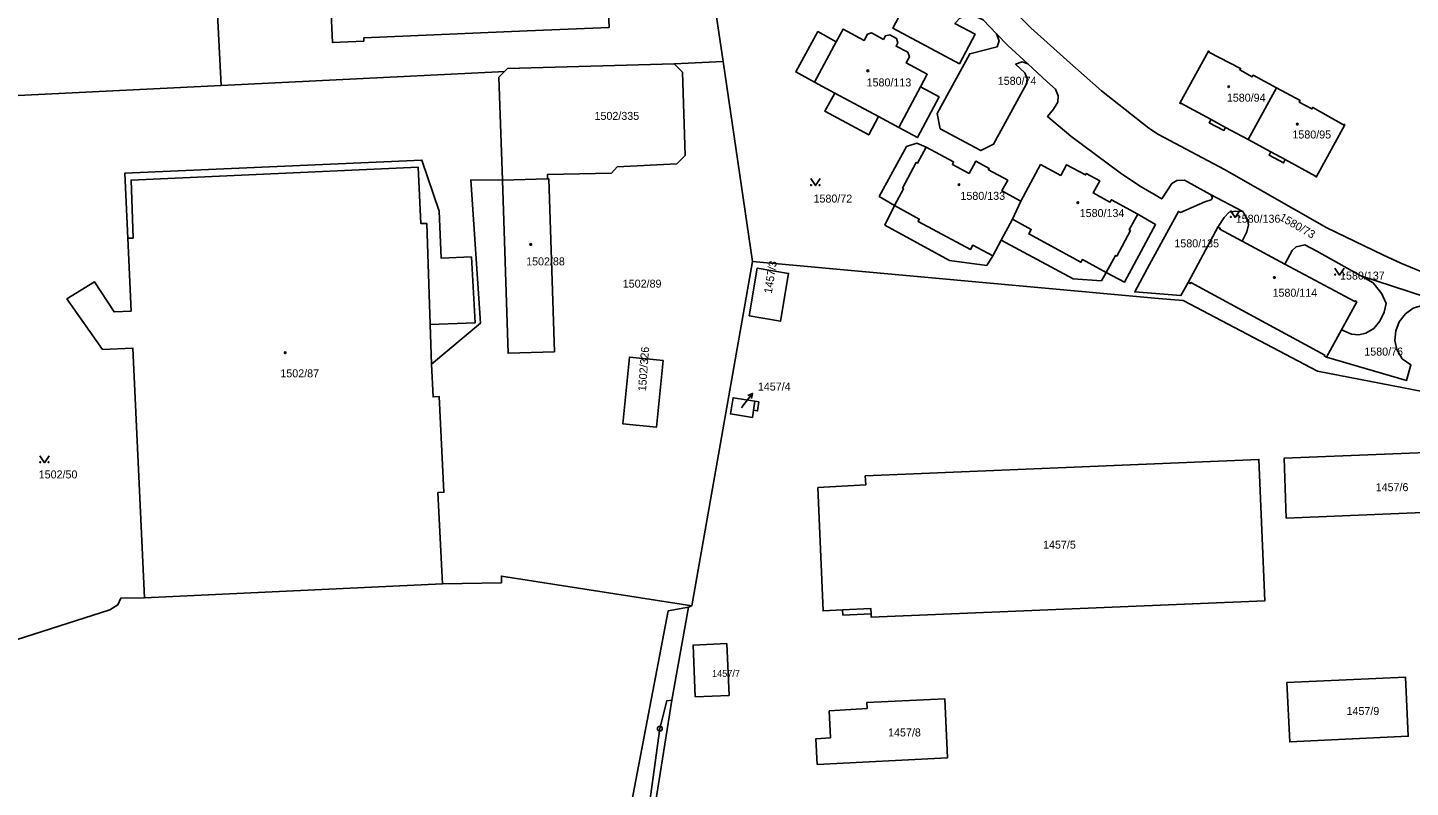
# Model space of a CAD drawing. Extents: x -737240 to -735272, y -1119606 to -1117878.
# Drawn here: x -736364.4 to -736070.6, y -1118481.5 to -1118320.2 of the extents above; entities that cross this region are included whole.
import ezdxf

# ---------------------------------------------------------------- set-up
doc = ezdxf.new("R2010")
doc.units = 0
for name, color, linetype in [('Level 1', 7, 'Continuous'), ('Level 16', 7, 'Continuous'), ('Level 18', 7, 'Continuous'), ('Level 19', 7, 'Continuous'), ('Level 25', 7, 'Continuous'), ('Level 4', 7, 'Continuous')]:
    doc.layers.add(name, color=color, linetype=linetype)

msp = doc.modelspace()

# ---------------------------------------------------------------- linework, layer by layer
at = {"layer": 'Level 1'}
for p, q in [((-736221.31, -1118295.84), (-736216.6, -1118327.37)), ((-736161.4, -1118318.52), (-736158.52, -1118321.48)), ((-736216.6, -1118327.37), (-736227.02, -1118327.84)), ((-736216.6, -1118327.37), (-736210.35, -1118369.86)), ((-736197.2, -1118331.72), (-736192.89, -1118334.04)), ((-736099.05, -1118332.96), (-736105.07, -1118343.93)), ((-736183.59, -1118339.04), (-736179.32, -1118341.34)), ((-736109.85, -1118341.34), (-736105.07, -1118343.93)), ((-736105.07, -1118343.93), (-736100.26, -1118346.53)), ((-736263.51, -1118352.52), (-736253.92, -1118352.29)), ((-736155.13, -1118360.86), (-736153.37, -1118357.01)), ((-736106.2, -1118359.23), (-736113.2, -1118355.5)), ((-736157.52, -1118365.27), (-736155.13, -1118360.86)), ((-736117.84, -1118374.26), (-736111.5, -1118362.52)), ((-736159.33, -1118368.64), (-736157.52, -1118365.27)), ((-736097.3, -1118370.36), (-736106.34, -1118365.52)), ((-736223.29, -1118442.99), (-736210.35, -1118369.86)), ((-736059.31, -1118379.99), (-736081.16, -1118372.84)), ((-736278.61, -1118391.65), (-736278.89, -1118383.2)), ((-736088.43, -1118390.14), (-736085.25, -1118384.34)), ((-736339.59, -1118441.28), (-736276.27, -1118438.27)), ((-736227.49, -1118462.99), (-736223.96, -1118443.23)), ((-736223.96, -1118443.23), (-736223.29, -1118442.99))]:
    msp.add_line(p, q, dxfattribs=at)
for points in [[(-736068.55, -1118371.85), (-736072.64, -1118370.2), (-736076.44, -1118368.41), (-736088.36, -1118362.67), (-736110.12, -1118350.32), (-736124.12, -1118342.88), (-736126.16, -1118341.48), (-736136.25, -1118333.56), (-736143.63, -1118327.06), (-736151.23, -1118320.2), (-736160.8, -1118310.46), (-736177.91, -1118292.84), (-736196.9, -1118273.97)], [(-736294.67, -1118283.81), (-736294.71, -1118283.08), (-736301.44, -1118283.43), (-736299.65, -1118323.31), (-736292.98, -1118323.01), (-736293, -1118322.34), (-736258.25, -1118320.8), (-736240.85, -1118320.09), (-736242.53, -1118281.51), (-736259.92, -1118282.25), (-736294.67, -1118283.81)], [(-736323.26, -1118332.43), (-736325.03, -1118297.95), (-736380.42, -1118300.27), (-736381.78, -1118300.94), (-736382.38, -1118302.33), (-736380.97, -1118335.25)], [(-736172.1, -1118307.65), (-736171, -1118309.11), (-736170.78, -1118310.09), (-736170.84, -1118311.64), (-736171.13, -1118312.71), (-736171.64, -1118313.71), (-736175.96, -1118311.46), (-736180.58, -1118320.28), (-736166.41, -1118327.84), (-736163.09, -1118321.53), (-736167.36, -1118319.29), (-736166.33, -1118318.15), (-736164.95, -1118317.56), (-736163.41, -1118317.56), (-736161.4, -1118318.52)], [(-736192.59, -1118323.14), (-736196.5, -1118320.98), (-736201.21, -1118329.56), (-736197.2, -1118331.72)], [(-736174.71, -1118332.75), (-736173.26, -1118330.06), (-736177.73, -1118327.66), (-736177.03, -1118326.38), (-736177.35, -1118325.39), (-736179.87, -1118324.1), (-736179.48, -1118323.4), (-736179.78, -1118322.45), (-736181.19, -1118321.68), (-736182.13, -1118321.87), (-736182.56, -1118322.65), (-736185.07, -1118321.29), (-736185.98, -1118321.55), (-736186.68, -1118322.85), (-736191.14, -1118320.45), (-736192.59, -1118323.14)], [(-736158.52, -1118321.48), (-736157.94, -1118322.93), (-736158.41, -1118324.22), (-736164.24, -1118325.69), (-736171.13, -1118338.38), (-736170.54, -1118341.64), (-736161.89, -1118346.28), (-736159.17, -1118344.92), (-736152.17, -1118332.06), (-736151.99, -1118330.98), (-736152.51, -1118329.78), (-736154.47, -1118327.94), (-736153.08, -1118327.41), (-736151.91, -1118327.84)], [(-736151.91, -1118327.84), (-736156.1, -1118323.97), (-736158.52, -1118321.48)], [(-736227.02, -1118327.84), (-736262.47, -1118328.86), (-736263.09, -1118329.48)], [(-736253.92, -1118352.29), (-736253.91, -1118351.34), (-736240.31, -1118351.05), (-736239.12, -1118349.69), (-736226.46, -1118349.08), (-736224.71, -1118347.31), (-736225.29, -1118329.61), (-736227.02, -1118327.84)], [(-736151.91, -1118327.84), (-736147.88, -1118331.57), (-736145.97, -1118333.22), (-736145.45, -1118334.65), (-736145.53, -1118336), (-736146.42, -1118337.49), (-736147.72, -1118339), (-736142.73, -1118343.24), (-736132.28, -1118350.99), (-736128.12, -1118353.73), (-736123.41, -1118356.52), (-736121.25, -1118353.28), (-736120.22, -1118352.62), (-736118.6, -1118352.53), (-736113.2, -1118355.5)], [(-736099.05, -1118332.96), (-736104.03, -1118330.26), (-736104.2, -1118330.57), (-736106.83, -1118329.14), (-736106.67, -1118328.83), (-736113.41, -1118325.36), (-736113.34, -1118325.22), (-736113.5, -1118325.14), (-736119.62, -1118336.2), (-736119.44, -1118336.3), (-736119.39, -1118336.19), (-736112.94, -1118339.68)], [(-736263.09, -1118329.48), (-736264.33, -1118329.54), (-736323.26, -1118332.43)], [(-736263.09, -1118329.48), (-736264.29, -1118330.68), (-736263.51, -1118352.52)], [(-736380.97, -1118335.25), (-736379.45, -1118335.18), (-736323.26, -1118332.43)], [(-736179.32, -1118341.34), (-736175.34, -1118343.49), (-736170.74, -1118334.88), (-736174.71, -1118332.75)], [(-736097.18, -1118348.19), (-736090.73, -1118351.68), (-736090.79, -1118351.78), (-736090.61, -1118351.88), (-736084.55, -1118340.79), (-736084.72, -1118340.69), (-736084.8, -1118340.83), (-736091.36, -1118337.1), (-736091.53, -1118337.41), (-736094.21, -1118335.96), (-736094.05, -1118335.66), (-736099.05, -1118332.96)], [(-736192.89, -1118334.04), (-736195.02, -1118337.92), (-736185.69, -1118342.95), (-736183.59, -1118339.04)], [(-736112.94, -1118339.68), (-736113.38, -1118340.34), (-736110.21, -1118342), (-736109.85, -1118341.34)], [(-736173.49, -1118345.53), (-736175.48, -1118344.7), (-736177.69, -1118345.4), (-736183.44, -1118355.99), (-736180.2, -1118357.95)], [(-736153.37, -1118357.01), (-736157.39, -1118354.84), (-736156.15, -1118352.56), (-736160.24, -1118350.34), (-736160.12, -1118350.05), (-736162.96, -1118348.52), (-736164.35, -1118351.11), (-736167.9, -1118349.19), (-736167.65, -1118348.66), (-736173.49, -1118345.53)], [(-736278.89, -1118383.2), (-736269.34, -1118382.88), (-736270.12, -1118368.85), (-736276.55, -1118369.1), (-736276.94, -1118359.16), (-736280.62, -1118348.27), (-736343.76, -1118351.09), (-736343.12, -1118364.89)], [(-736100.26, -1118346.53), (-736100.63, -1118347.21), (-736097.55, -1118348.88), (-736097.18, -1118348.19)], [(-736128.51, -1118359.75), (-736134.13, -1118356.71), (-736134.43, -1118357.19), (-736137.97, -1118355.27), (-736136.61, -1118352.7), (-736139.47, -1118351.16), (-736139.62, -1118351.44), (-736143.64, -1118349.26), (-736144.88, -1118351.55), (-736149.18, -1118349.24), (-736153.37, -1118357.01)], [(-736263.51, -1118352.52), (-736270.26, -1118352.5), (-736268.18, -1118382.94), (-736278.61, -1118391.65)], [(-736253.92, -1118352.29), (-736253.63, -1118352.28), (-736252.49, -1118389.01), (-736262.31, -1118389.33), (-736263.51, -1118352.52)], [(-736113.2, -1118355.5), (-736112.91, -1118355.84), (-736112.66, -1118356.27), (-736112.96, -1118356.7), (-736114.3, -1118357.13), (-736119.42, -1118359.4), (-736119.87, -1118359.2), (-736126.02, -1118370.43), (-736129.18, -1118376.27), (-736119.36, -1118377.08), (-736117.84, -1118374.26)], [(-736180.2, -1118357.95), (-736182.26, -1118362.08), (-736168.54, -1118369.59), (-736160.62, -1118370.71), (-736159.33, -1118368.64)], [(-736135.22, -1118372.18), (-736131.36, -1118374.21), (-736124.74, -1118361.99), (-736128.51, -1118359.75)], [(-736111.5, -1118362.52), (-736110.16, -1118360.45), (-736109.08, -1118359.37), (-736107.74, -1118359.11), (-736106.2, -1118359.23)], [(-736106.34, -1118365.52), (-736105.32, -1118363.55), (-736105.02, -1118362.06), (-736105.2, -1118360.89), (-736106.2, -1118359.23)], [(-736111.5, -1118362.52), (-736110.97, -1118362.8), (-736111.07, -1118362.98), (-736106.34, -1118365.52)], [(-736343.12, -1118364.89), (-736342.41, -1118380.37), (-736346.04, -1118380.54), (-736350.21, -1118374.13), (-736356.05, -1118377.76), (-736348.49, -1118388.51), (-736342.05, -1118388.21), (-736339.59, -1118441.28)], [(-736157.52, -1118365.27), (-736142.22, -1118373.5), (-736136.24, -1118373.94), (-736135.22, -1118372.18)], [(-736081.16, -1118372.84), (-736090.47, -1118367.63), (-736093, -1118366.28), (-736094.89, -1118366.69), (-736095.7, -1118367.46), (-736097.3, -1118370.36)], [(-736211.1, -1118381.39), (-736204.47, -1118382.53), (-736202.72, -1118372.35), (-736209.36, -1118371.23), (-736211.1, -1118381.39)], [(-736210.35, -1118369.86), (-736124.09, -1118377.65), (-736118.86, -1118378.12), (-736090.36, -1118393.09), (-736052.32, -1118400.48), (-736052.29, -1118402.89)], [(-736097.3, -1118370.36), (-736082.42, -1118378.34), (-736082.32, -1118378.16), (-736081.99, -1118378.4), (-736085.25, -1118384.34)], [(-736117.84, -1118374.26), (-736117.36, -1118374.52), (-736117.25, -1118374.31), (-736088.8, -1118389.69), (-736088.91, -1118389.89), (-736088.43, -1118390.14)], [(-736085.25, -1118384.34), (-736083.12, -1118385.26), (-736081.56, -1118385.38), (-736080.07, -1118385.07), (-736078.33, -1118384.05), (-736077.1, -1118382.53), (-736076.18, -1118380.62), (-736075.77, -1118378.73), (-736076.63, -1118376.68), (-736078.53, -1118374.33), (-736081.16, -1118372.84)], [(-736088.43, -1118390.14), (-736071.45, -1118395.11), (-736070.47, -1118391.75), (-736072.34, -1118390.47), (-736073.5, -1118388.55), (-736073.92, -1118386.61), (-736073.71, -1118384.56), (-736072.98, -1118382.66), (-736071.67, -1118380.97), (-736070.03, -1118379.76), (-736067.91, -1118379.12), (-736065.33, -1118379.12), (-736059.31, -1118379.99)], [(-736278.61, -1118391.65), (-736278.26, -1118398.58), (-736276.96, -1118398.51), (-736275.94, -1118418.85), (-736277.24, -1118418.92), (-736276.27, -1118438.27)], [(-736229.36, -1118390.85), (-736236.53, -1118390.14), (-736237.93, -1118404.33), (-736230.76, -1118404.99), (-736229.36, -1118390.85)], [(-736209.91, -1118399.5), (-736214.52, -1118398.76), (-736215.07, -1118402.21), (-736210.39, -1118402.94), (-736210.18, -1118401.41)], [(-736210.18, -1118401.41), (-736209.3, -1118401.55), (-736209.05, -1118399.64), (-736209.91, -1118399.5)], [(-736054.56, -1118414.79), (-736054.76, -1118409.87), (-736097.43, -1118411.63), (-736096.98, -1118424.31), (-736054.24, -1118422.54), (-736054.44, -1118417.58)], [(-736185.18, -1118444.69), (-736185.15, -1118445.39), (-736101.51, -1118441.88), (-736102.77, -1118411.87), (-736186.41, -1118415.38), (-736186.33, -1118417.24), (-736196.5, -1118417.85), (-736195.37, -1118444.04), (-736191.24, -1118443.78)], [(-736276.27, -1118438.27), (-736263.74, -1118438.05), (-736263.74, -1118436.64), (-736223.29, -1118442.99)], [(-736339.59, -1118441.28), (-736344.61, -1118441.35), (-736345.27, -1118442.76), (-736346.97, -1118443.8), (-736372.19, -1118451.87), (-736373.71, -1118451.92)], [(-736223.96, -1118443.23), (-736228.27, -1118444.06), (-736245.05, -1118531.56), (-736245.39, -1118532.38), (-736246.89, -1118533.59), (-736374.05, -1118539.63)], [(-736191.24, -1118443.78), (-736191.19, -1118444.94), (-736185.18, -1118444.69)], [(-736222.55, -1118462.28), (-736215.36, -1118461.99), (-736215.86, -1118450.97), (-736223, -1118451.3), (-736222.55, -1118462.28)], [(-736096.82, -1118459.28), (-736096.23, -1118471.87), (-736071.05, -1118470.65), (-736071.66, -1118458.08), (-736096.82, -1118459.28)], [(-736251.91, -1118694.01), (-736247.64, -1118635.96), (-736244.25, -1118594.56), (-736239.9, -1118543.95), (-736237.36, -1118522.21), (-736230.07, -1118469.05), (-736228.6, -1118463.11), (-736227.49, -1118462.99)], [(-736234.35, -1118589.01), (-736236.91, -1118522.19), (-736227.49, -1118462.99)], [(-736194.09, -1118465.26), (-736193.84, -1118470.99), (-736196.91, -1118471.19), (-736196.63, -1118476.66), (-736168.94, -1118475.23), (-736169.53, -1118462.71), (-736186.08, -1118463.47), (-736186.05, -1118464.76), (-736194.09, -1118465.26)]]:
    msp.add_lwpolyline(points, dxfattribs=at)
at = {"layer": 'Level 16'}
for points in [[(-736212.74, -1118400.9), (-736212.2, -1118400.2), (-736210.362, -1118397.829)], [(-736211.37, -1118398.313), (-736210.362, -1118397.829), (-736210.579, -1118398.926)]]:
    msp.add_lwpolyline(points, dxfattribs=at)
at = {"layer": 'Level 25'}
for points in [[(-736196.02, -1118352.21), (-736197.02, -1118353.71), (-736198.02, -1118352.21)], [(-736106.83, -1118358.96), (-736107.83, -1118360.46), (-736108.83, -1118358.96)], [(-736084.66, -1118371.21), (-736085.66, -1118372.71), (-736086.66, -1118371.21)], [(-736359.84, -1118411.07), (-736360.84, -1118412.57), (-736361.84, -1118411.07)]]:
    msp.add_lwpolyline(points, dxfattribs=at)
for centre in [(-736197.92, -1118353.61), (-736196.12, -1118353.61), (-736108.73, -1118360.36), (-736106.93, -1118360.36), (-736086.56, -1118372.61), (-736084.76, -1118372.61), (-736361.74, -1118412.47), (-736359.94, -1118412.47)]:
    msp.add_circle(centre, 0.1, dxfattribs=at)
for centre, major_axis in [((-736185.88, -1118329.32), (0.18, 0)), ((-736109.21, -1118332.7), (0.18, 0)), ((-736094.61, -1118340.65), (0.18, 0)), ((-736166.51, -1118353.51), (0.18, 0)), ((-736141.24, -1118357.34), (0.18, 0)), ((-736257.5, -1118366.21), (0.18, 0)), ((-736099.5, -1118373.23), (-0.179, 0.02)), ((-736309.67, -1118389.19), (0.18, 0)), ((-736230.07, -1118469.05), (0.516, 0)), ((-736230.07, -1118469.05), (0.0375, 0))]:
    msp.add_ellipse(centre, major_axis=major_axis, ratio=0.9848078, dxfattribs=at)
at = {"layer": 'Level 4'}
for p, q in [((-736197.2, -1118331.72), (-736192.59, -1118323.14)), ((-736179.32, -1118341.34), (-736174.71, -1118332.75)), ((-736192.89, -1118334.04), (-736183.59, -1118339.04)), ((-736112.94, -1118339.68), (-736109.85, -1118341.34)), ((-736100.26, -1118346.53), (-736097.18, -1118348.19)), ((-736210.18, -1118401.41), (-736209.91, -1118399.5))]:
    msp.add_line(p, q, dxfattribs=at)
for points in [[(-736173.49, -1118345.53), (-736175.31, -1118348.91), (-736175.59, -1118348.78), (-736178.54, -1118354.25), (-736178.27, -1118354.41), (-736180.2, -1118357.95)], [(-736343.12, -1118364.89), (-736341.99, -1118364.84), (-736342.44, -1118352.53), (-736281.39, -1118349.79), (-736280.85, -1118361.78), (-736279.6, -1118361.72), (-736278.89, -1118383.2)], [(-736180.2, -1118357.95), (-736174.95, -1118360.81), (-736175.19, -1118361.33), (-736164.07, -1118367.3), (-736163.58, -1118366.38), (-736159.33, -1118368.64)], [(-736135.22, -1118372.18), (-736133.24, -1118368.55), (-736132.98, -1118368.67), (-736130.08, -1118363.27), (-736130.35, -1118363.11), (-736128.51, -1118359.75)], [(-736155.13, -1118360.86), (-736151.16, -1118363), (-736151.69, -1118363.96), (-736140.59, -1118369.97), (-736140.27, -1118369.43), (-736135.22, -1118372.18)], [(-736191.24, -1118443.78), (-736185.23, -1118443.53), (-736185.18, -1118444.69)]]:
    msp.add_lwpolyline(points, dxfattribs=at)

# ---------------------------------------------------------------- texts
at = {"layer": 'Level 16'}
msp.add_text('1457/4', height=1.7, dxfattribs=at).set_placement((-736209.24, -1118397.24))
at = {"layer": 'Level 18'}
for s, height, p in [('1580/74', 1.7, (-736158.265, -1118332.3)), ('1502/335', 1.7, (-736243.95, -1118339.75)), ('1580/72', 1.7, (-736197.415, -1118357.31)), ('1580/136', 1.7, (-736107.7, -1118361.59)), ('1580/135', 1.7, (-736120.74, -1118366.82)), ('1580/137', 1.7, (-736085.54, -1118373.67)), ('1502/89', 1.7, (-736237.945, -1118375.38)), ('1580/76', 1.7, (-736080.385, -1118389.81)), ('1457/4', 0.1, (-736212.74, -1118400.9)), ('1502/50', 1.7, (-736362.045, -1118415.9)), ('1457/6', 1.7, (-736077.97, -1118418.61)), ('1457/5', 1.7, (-736148.64, -1118430.82)), ('1457/7', 1.45, (-736218.98, -1118458.06)), ('1457/9', 1.7, (-736084.16, -1118466.15)), ('1457/8', 1.7, (-736181.57, -1118470.71))]:
    msp.add_text(s, height=height, dxfattribs=at).set_placement(p)
for s, rotation, p in [('1580/73', 330.20082, (-736098.578, -1118360.928)), ('1457/3', 80.71047, (-736206.29, -1118376.71)), ('1502/326', 85.90932, (-736233.02, -1118397.45))]:
    msp.add_text(s, height=1.7, rotation=rotation, dxfattribs=at).set_placement(p)
at = {"layer": 'Level 19'}
for s, p in [('1580/113', (-736186.135, -1118332.64)), ('1580/94', (-736109.59, -1118335.88)), ('1580/95', (-736095.66, -1118343.7)), ('1580/133', (-736166.2, -1118356.73)), ('1580/134', (-736140.86, -1118360.39)), ('1502/88', (-736258.48, -1118370.65)), ('1580/114', (-736099.885, -1118377.31)), ('1502/87', (-736310.7, -1118394.43))]:
    msp.add_text(s, height=1.7, dxfattribs=at).set_placement(p)

doc.saveas('drawing.dxf')
